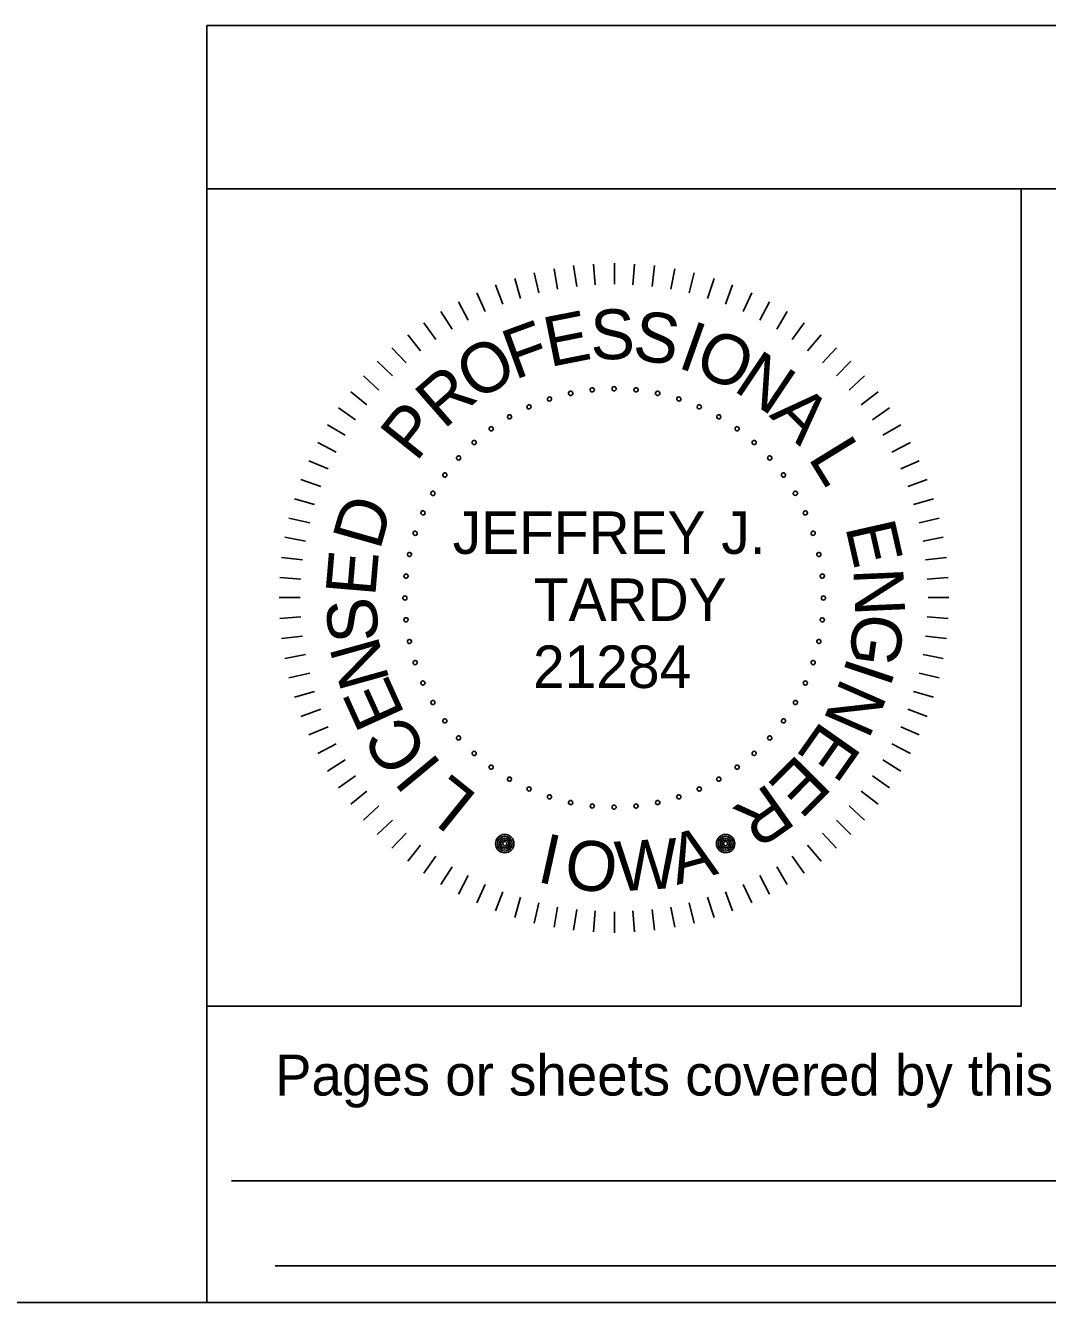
# Model space of a CAD drawing. Extents: x -2096698 to 6160, y -2144490 to 6200.
# Drawn here: x 5321.7 to 5625.4, y 4209 to 4588.6 of the extents above; entities that cross this region are included whole.
import ezdxf

# ---------------------------------------------------------------- set-up
doc = ezdxf.new("R2010")
doc.units = 0
doc.layers.add('Level 15', color=7, linetype='Continuous')
doc.layers.add('Level 2', color=7, linetype='Continuous')

msp = doc.modelspace()

# ---------------------------------------------------------------- linework, layer by layer
at = {"layer": 'Level 15'}
msp.add_line((3074.9, 4208.97), (6131.53, 4208.97), dxfattribs=at)
at = {"layer": 'Level 2'}
for p, q in [((5375.6, 4540.02), (6131.53, 4540.02)), ((5617.5, 4297.05), (5617.5, 4540.02)), ((5496.67, 4511.73), (5496.67, 4517.93)), ((5496.67, 4511.73), (5496.67, 4517.93)), ((5474.21, 4509.11), (5472.79, 4515.07)), ((5474.21, 4509.11), (5472.79, 4515.07)), ((5479.71, 4510.28), (5478.75, 4516.26)), ((5479.71, 4510.28), (5478.75, 4516.26)), ((5485.46, 4511.01), (5484.48, 4517.23)), ((5485.46, 4511.01), (5484.48, 4517.23)), ((5490.94, 4511.5), (5490.47, 4517.69)), ((5490.94, 4511.5), (5490.47, 4517.69)), ((5502.17, 4511.5), (5502.66, 4517.69)), ((5502.17, 4511.5), (5502.66, 4517.69)), ((5507.92, 4511.01), (5508.62, 4517.23)), ((5507.92, 4511.01), (5508.62, 4517.23)), ((5513.4, 4510.28), (5514.6, 4516.26)), ((5513.4, 4510.28), (5514.6, 4516.26)), ((5518.89, 4509.11), (5520.33, 4515.07)), ((5518.89, 4509.11), (5520.33, 4515.07)), ((5463.47, 4505.74), (5461.31, 4511.5)), ((5463.47, 4505.74), (5461.31, 4511.5)), ((5468.72, 4507.43), (5467.04, 4513.4)), ((5468.72, 4507.43), (5467.04, 4513.4)), ((5524.38, 4507.43), (5526.29, 4513.4)), ((5524.38, 4507.43), (5526.29, 4513.4)), ((5529.67, 4505.74), (5531.8, 4511.5)), ((5529.67, 4505.74), (5531.8, 4511.5)), ((5453.2, 4500.98), (5450.33, 4506.48)), ((5453.2, 4500.98), (5450.33, 4506.48)), ((5458.22, 4503.6), (5455.83, 4509.11)), ((5458.22, 4503.6), (5455.83, 4509.11)), ((5534.92, 4503.6), (5537.54, 4509.11)), ((5534.92, 4503.6), (5537.54, 4509.11)), ((5539.93, 4500.98), (5542.8, 4506.48)), ((5539.93, 4500.98), (5542.8, 4506.48)), ((5448.42, 4498.34), (5445.06, 4503.6)), ((5448.42, 4498.34), (5445.06, 4503.6)), ((5544.95, 4498.34), (5548.05, 4503.6)), ((5544.95, 4498.34), (5548.05, 4503.6)), ((5443.63, 4495.23), (5440.07, 4500.25)), ((5443.63, 4495.23), (5440.07, 4500.25)), ((5549.48, 4495.23), (5553.07, 4500.25)), ((5549.48, 4495.23), (5553.07, 4500.25)), ((5439.08, 4491.9), (5435.28, 4496.68)), ((5439.08, 4491.9), (5435.28, 4496.68)), ((5554.01, 4491.9), (5558.08, 4496.68)), ((5554.01, 4491.9), (5558.08, 4496.68)), ((5434.78, 4488.3), (5430.5, 4492.84)), ((5434.78, 4488.3), (5430.5, 4492.84)), ((5558.55, 4488.3), (5562.62, 4492.84)), ((5558.55, 4488.3), (5562.62, 4492.84)), ((5430.73, 4484.49), (5426.19, 4488.79)), ((5430.73, 4484.49), (5426.19, 4488.79)), ((5562.62, 4484.49), (5566.92, 4488.79)), ((5562.62, 4484.49), (5566.92, 4488.79)), ((5426.66, 4480.18), (5422.14, 4484.49)), ((5426.66, 4480.18), (5422.14, 4484.49)), ((5566.44, 4480.18), (5570.98, 4484.49)), ((5566.44, 4480.18), (5570.98, 4484.49)), ((5423.09, 4475.88), (5418.32, 4479.72)), ((5423.09, 4475.88), (5418.32, 4479.72)), ((5570.03, 4475.88), (5575.06, 4479.72)), ((5570.03, 4475.88), (5575.06, 4479.72)), ((5419.75, 4471.35), (5414.71, 4474.93)), ((5419.75, 4471.35), (5414.71, 4474.93)), ((5573.37, 4471.35), (5578.38, 4474.93)), ((5573.37, 4471.35), (5578.38, 4474.93)), ((5416.63, 4466.82), (5411.38, 4469.92)), ((5416.63, 4466.82), (5411.38, 4469.92)), ((5576.47, 4466.82), (5581.74, 4469.92)), ((5576.47, 4466.82), (5581.74, 4469.92)), ((5414, 4461.8), (5408.52, 4464.67)), ((5414, 4461.8), (5408.52, 4464.67)), ((5579.11, 4461.8), (5584.62, 4464.67)), ((5579.11, 4461.8), (5584.62, 4464.67)), ((5411.61, 4456.78), (5405.89, 4459.17)), ((5411.61, 4456.78), (5405.89, 4459.17)), ((5581.74, 4456.78), (5587.24, 4459.17)), ((5581.74, 4456.78), (5587.24, 4459.17)), ((5409.46, 4451.53), (5403.5, 4453.67)), ((5409.46, 4451.53), (5403.5, 4453.67)), ((5583.88, 4451.53), (5589.63, 4453.67)), ((5583.88, 4451.53), (5589.63, 4453.67)), ((5407.56, 4446.24), (5401.58, 4447.93)), ((5407.56, 4446.24), (5401.58, 4447.93)), ((5585.56, 4446.24), (5591.54, 4447.93)), ((5585.56, 4446.24), (5591.54, 4447.93)), ((5406.13, 4440.76), (5399.91, 4442.2)), ((5406.13, 4440.76), (5399.91, 4442.2)), ((5587.24, 4440.76), (5593.2, 4442.2)), ((5587.24, 4440.76), (5593.2, 4442.2)), ((5404.91, 4435.27), (5398.72, 4436.46)), ((5404.91, 4435.27), (5398.72, 4436.46)), ((5588.42, 4435.27), (5594.4, 4436.46)), ((5588.42, 4435.27), (5594.4, 4436.46)), ((5403.97, 4429.78), (5397.76, 4430.48)), ((5403.97, 4429.78), (5397.76, 4430.48)), ((5589.15, 4429.78), (5595.36, 4430.48)), ((5589.15, 4429.78), (5595.36, 4430.48)), ((5403.5, 4424.04), (5397.27, 4424.52)), ((5403.5, 4424.04), (5397.27, 4424.52)), ((5589.63, 4424.04), (5595.83, 4424.52)), ((5589.63, 4424.04), (5595.83, 4424.52)), ((5403.26, 4418.54), (5397.04, 4418.54)), ((5403.26, 4418.54), (5397.04, 4418.54)), ((5589.87, 4418.54), (5596.06, 4418.54)), ((5589.87, 4418.54), (5596.06, 4418.54)), ((5403.5, 4412.81), (5397.27, 4412.33)), ((5403.5, 4412.81), (5397.27, 4412.33)), ((5589.63, 4412.81), (5595.83, 4412.33)), ((5589.63, 4412.81), (5595.83, 4412.33)), ((5403.97, 4407.08), (5397.76, 4406.34)), ((5403.97, 4407.08), (5397.76, 4406.34)), ((5589.15, 4407.08), (5595.36, 4406.34)), ((5589.15, 4407.08), (5595.36, 4406.34)), ((5404.91, 4401.58), (5398.72, 4400.38)), ((5404.91, 4401.58), (5398.72, 4400.38)), ((5588.42, 4401.58), (5594.4, 4400.38)), ((5588.42, 4401.58), (5594.4, 4400.38)), ((5406.13, 4396.08), (5399.91, 4394.66)), ((5406.13, 4396.08), (5399.91, 4394.66)), ((5587.24, 4396.08), (5593.2, 4394.66)), ((5587.24, 4396.08), (5593.2, 4394.66)), ((5407.56, 4390.58), (5401.58, 4388.9)), ((5407.56, 4390.58), (5401.58, 4388.9)), ((5585.56, 4390.58), (5591.54, 4388.9)), ((5585.56, 4390.58), (5591.54, 4388.9)), ((5409.46, 4385.33), (5403.5, 4383.18)), ((5409.46, 4385.33), (5403.5, 4383.18)), ((5583.88, 4385.33), (5589.63, 4383.18)), ((5583.88, 4385.33), (5589.63, 4383.18)), ((5411.61, 4380.08), (5405.89, 4377.69)), ((5411.61, 4380.08), (5405.89, 4377.69)), ((5581.74, 4380.08), (5587.24, 4377.69)), ((5581.74, 4380.08), (5587.24, 4377.69)), ((5414, 4375.07), (5408.52, 4372.2)), ((5414, 4375.07), (5408.52, 4372.2)), ((5579.11, 4375.07), (5584.62, 4372.2)), ((5579.11, 4375.07), (5584.62, 4372.2)), ((5416.63, 4370.28), (5411.38, 4366.93)), ((5416.63, 4370.28), (5411.38, 4366.93)), ((5576.47, 4370.28), (5581.74, 4366.93)), ((5576.47, 4370.28), (5581.74, 4366.93)), ((5419.75, 4365.5), (5414.71, 4361.93)), ((5419.75, 4365.5), (5414.71, 4361.93)), ((5573.37, 4365.5), (5578.38, 4361.93)), ((5573.37, 4365.5), (5578.38, 4361.93)), ((5423.09, 4360.95), (5418.32, 4357.15)), ((5423.09, 4360.95), (5418.32, 4357.15)), ((5570.03, 4360.95), (5575.06, 4357.15)), ((5570.03, 4360.95), (5575.06, 4357.15)), ((5426.66, 4356.64), (5422.14, 4352.37)), ((5426.66, 4356.64), (5422.14, 4352.37)), ((5566.44, 4356.64), (5570.98, 4352.37)), ((5566.44, 4356.64), (5570.98, 4352.37)), ((5430.73, 4352.37), (5426.19, 4348.06)), ((5430.73, 4352.37), (5426.19, 4348.06)), ((5562.62, 4352.37), (5566.92, 4348.06)), ((5562.62, 4352.37), (5566.92, 4348.06)), ((5434.78, 4348.53), (5430.5, 4344)), ((5434.78, 4348.53), (5430.5, 4344)), ((5558.55, 4348.53), (5562.62, 4344)), ((5558.55, 4348.53), (5562.62, 4344)), ((5439.08, 4344.96), (5435.28, 4340.18)), ((5439.08, 4344.96), (5435.28, 4340.18)), ((5554.01, 4344.96), (5558.08, 4340.18)), ((5554.01, 4344.96), (5558.08, 4340.18)), ((5443.63, 4341.61), (5440.07, 4336.58)), ((5443.63, 4341.61), (5440.07, 4336.58)), ((5549.48, 4341.61), (5553.07, 4336.58)), ((5549.48, 4341.61), (5553.07, 4336.58)), ((5448.42, 4338.49), (5445.06, 4333.24)), ((5448.42, 4338.49), (5445.06, 4333.24)), ((5453.2, 4335.87), (5450.33, 4330.38)), ((5453.2, 4335.87), (5450.33, 4330.38)), ((5539.93, 4335.87), (5542.8, 4330.38)), ((5539.93, 4335.87), (5542.8, 4330.38)), ((5544.95, 4338.49), (5548.05, 4333.24)), ((5544.95, 4338.49), (5548.05, 4333.24)), ((5458.22, 4333.24), (5455.83, 4327.76)), ((5458.22, 4333.24), (5455.83, 4327.76)), ((5534.92, 4333.24), (5537.54, 4327.76)), ((5534.92, 4333.24), (5537.54, 4327.76)), ((5463.47, 4331.08), (5461.31, 4325.37)), ((5463.47, 4331.08), (5461.31, 4325.37)), ((5468.72, 4329.42), (5467.04, 4323.44)), ((5468.72, 4329.42), (5467.04, 4323.44)), ((5524.38, 4329.42), (5526.29, 4323.44)), ((5524.38, 4329.42), (5526.29, 4323.44)), ((5529.67, 4331.08), (5531.8, 4325.37)), ((5529.67, 4331.08), (5531.8, 4325.37)), ((5474.21, 4327.76), (5472.79, 4321.78)), ((5474.21, 4327.76), (5472.79, 4321.78)), ((5479.71, 4326.54), (5478.75, 4320.58)), ((5479.71, 4326.54), (5478.75, 4320.58)), ((5485.46, 4325.83), (5484.48, 4319.62)), ((5485.46, 4325.83), (5484.48, 4319.62)), ((5490.94, 4325.37), (5490.47, 4319.14)), ((5490.94, 4325.37), (5490.47, 4319.14)), ((5496.67, 4325.12), (5496.67, 4318.9)), ((5496.67, 4325.12), (5496.67, 4318.9)), ((5502.17, 4325.37), (5502.66, 4319.14)), ((5502.17, 4325.37), (5502.66, 4319.14)), ((5507.92, 4325.83), (5508.62, 4319.62)), ((5507.92, 4325.83), (5508.62, 4319.62)), ((5513.4, 4326.54), (5514.6, 4320.58)), ((5513.4, 4326.54), (5514.6, 4320.58)), ((5518.89, 4327.76), (5520.33, 4321.78)), ((5518.89, 4327.76), (5520.33, 4321.78)), ((5375.6, 4297.05), (5617.5, 4297.05)), ((5382.93, 4245.18), (6123.89, 4245.18)), ((5395.82, 4219.87), (6111.37, 4219.87))]:
    msp.add_line(p, q, dxfattribs=at)
msp.add_lwpolyline([(5375.6, 4588.62), (6131.53, 4588.62), (6131.53, 4208.97), (5375.6, 4208.97)], close=True, dxfattribs=at)
for centre, radius in [((5464.09, 4345.38), 2.73), ((5464.09, 4345.38), 2.73), ((5464.09, 4345.38), 2.19), ((5464.09, 4345.38), 2.19), ((5464.09, 4345.38), 1.64), ((5464.09, 4345.38), 1.64), ((5529.72, 4345.38), 2.73), ((5529.72, 4345.38), 2.73), ((5529.72, 4345.38), 2.19), ((5529.72, 4345.38), 2.19), ((5529.72, 4345.38), 1.64), ((5529.72, 4345.38), 1.64), ((5464.09, 4345.38), 1.17), ((5464.09, 4345.38), 1.17), ((5529.72, 4345.38), 1.17), ((5529.72, 4345.38), 1.17)]:
    msp.add_circle(centre, radius, dxfattribs=at)
for centre, start, end in [((5483.66, 4479.27), 12, 192), ((5483.66, 4479.27), 12, 192), ((5490.09, 4480.29), 6, 186), ((5490.09, 4480.29), 6, 186), ((5490.09, 4480.29), 186, 6), ((5490.09, 4480.29), 186, 6), ((5496.59, 4480.63), 0, 180), ((5496.59, 4480.63), 0, 180), ((5496.59, 4480.63), 180, 0), ((5496.59, 4480.63), 180, 0), ((5503.1, 4480.29), 174, 354), ((5503.1, 4480.29), 174, 354), ((5503.1, 4480.29), 354, 174), ((5503.1, 4480.29), 354, 174), ((5509.53, 4479.27), 348, 168), ((5509.53, 4479.27), 348, 168), ((5477.37, 4477.58), 18, 198), ((5477.37, 4477.58), 18, 198), ((5477.37, 4477.58), 198, 18), ((5477.37, 4477.58), 198, 18), ((5483.66, 4479.27), 192, 12), ((5483.66, 4479.27), 192, 12), ((5509.53, 4479.27), 168, 348), ((5509.53, 4479.27), 168, 348), ((5515.81, 4477.58), 162, 342), ((5515.81, 4477.58), 162, 342), ((5515.81, 4477.58), 342, 162), ((5515.81, 4477.58), 342, 162), ((5465.5, 4472.3), 30, 210), ((5465.5, 4472.3), 30, 210), ((5465.5, 4472.3), 210, 30), ((5465.5, 4472.3), 210, 30), ((5471.3, 4475.25), 24, 204), ((5471.3, 4475.25), 24, 204), ((5471.3, 4475.25), 204, 24), ((5471.3, 4475.25), 204, 24), ((5521.89, 4475.25), 156, 336), ((5521.89, 4475.25), 156, 336), ((5521.89, 4475.25), 336, 156), ((5521.89, 4475.25), 336, 156), ((5527.69, 4472.3), 150, 330), ((5527.69, 4472.3), 150, 330), ((5527.69, 4472.3), 330, 150), ((5527.69, 4472.3), 330, 150), ((5460.04, 4468.75), 36, 216), ((5460.04, 4468.75), 36, 216), ((5460.04, 4468.75), 216, 36), ((5460.04, 4468.75), 216, 36), ((5533.15, 4468.75), 144, 324), ((5533.15, 4468.75), 144, 324), ((5533.15, 4468.75), 324, 144), ((5533.15, 4468.75), 324, 144), ((5454.98, 4464.65), 42, 222), ((5454.98, 4464.65), 42, 222), ((5454.98, 4464.65), 222, 42), ((5454.98, 4464.65), 222, 42), ((5538.21, 4464.65), 138, 318), ((5538.21, 4464.65), 138, 318), ((5538.21, 4464.65), 318, 138), ((5538.21, 4464.65), 318, 138), ((5450.37, 4460.05), 48, 228), ((5450.37, 4460.05), 48, 228), ((5450.37, 4460.05), 228, 48), ((5450.37, 4460.05), 228, 48), ((5542.82, 4460.05), 132, 312), ((5542.82, 4460.05), 132, 312), ((5542.82, 4460.05), 312, 132), ((5542.82, 4460.05), 312, 132), ((5446.28, 4454.99), 54, 234), ((5446.28, 4454.99), 54, 234), ((5446.28, 4454.99), 234, 54), ((5446.28, 4454.99), 234, 54), ((5546.91, 4454.99), 126, 306), ((5546.91, 4454.99), 126, 306), ((5546.91, 4454.99), 306, 126), ((5546.91, 4454.99), 306, 126), ((5442.73, 4449.53), 60, 240), ((5442.73, 4449.53), 60, 240), ((5442.73, 4449.53), 240, 60), ((5442.73, 4449.53), 240, 60), ((5550.46, 4449.53), 120, 300), ((5550.46, 4449.53), 120, 300), ((5550.46, 4449.53), 300, 120), ((5550.46, 4449.53), 300, 120), ((5439.77, 4443.73), 66, 246), ((5439.77, 4443.73), 66, 246), ((5439.77, 4443.73), 246, 66), ((5439.77, 4443.73), 246, 66), ((5553.41, 4443.73), 114, 294), ((5553.41, 4443.73), 114, 294), ((5553.41, 4443.73), 294, 114), ((5553.41, 4443.73), 294, 114), ((5437.44, 4437.65), 72, 252), ((5437.44, 4437.65), 72, 252), ((5437.44, 4437.65), 252, 72), ((5437.44, 4437.65), 252, 72), ((5555.75, 4437.65), 108, 288), ((5555.75, 4437.65), 108, 288), ((5555.75, 4437.65), 288, 108), ((5555.75, 4437.65), 288, 108), ((5435.76, 4431.36), 78, 258), ((5435.76, 4431.36), 78, 258), ((5435.76, 4431.36), 258, 78), ((5435.76, 4431.36), 258, 78), ((5557.43, 4431.36), 102, 282), ((5557.43, 4431.36), 102, 282), ((5557.43, 4431.36), 282, 102), ((5557.43, 4431.36), 282, 102), ((5434.74, 4424.93), 84, 264), ((5434.74, 4424.93), 84, 264), ((5434.74, 4424.93), 264, 84), ((5434.74, 4424.93), 264, 84), ((5558.45, 4424.93), 96, 276), ((5558.45, 4424.93), 96, 276), ((5558.45, 4424.93), 276, 96), ((5558.45, 4424.93), 276, 96), ((5434.4, 4418.43), 90, 270), ((5434.4, 4418.43), 90, 270), ((5434.4, 4418.43), 270, 90), ((5434.4, 4418.43), 270, 90), ((5558.79, 4418.43), 90, 270), ((5558.79, 4418.43), 90, 270), ((5558.79, 4418.43), 270, 90), ((5558.79, 4418.43), 270, 90), ((5434.74, 4411.93), 96, 276), ((5434.74, 4411.93), 96, 276), ((5434.74, 4411.93), 276, 96), ((5434.74, 4411.93), 276, 96), ((5558.45, 4411.93), 84, 264), ((5558.45, 4411.93), 84, 264), ((5558.45, 4411.93), 264, 84), ((5558.45, 4411.93), 264, 84), ((5435.76, 4405.5), 102, 282), ((5435.76, 4405.5), 102, 282), ((5435.76, 4405.5), 282, 102), ((5435.76, 4405.5), 282, 102), ((5557.43, 4405.5), 78, 258), ((5557.43, 4405.5), 78, 258), ((5557.43, 4405.5), 258, 78), ((5557.43, 4405.5), 258, 78), ((5437.44, 4399.21), 108, 288), ((5437.44, 4399.21), 108, 288), ((5437.44, 4399.21), 288, 108), ((5437.44, 4399.21), 288, 108), ((5555.75, 4399.21), 72, 252), ((5555.75, 4399.21), 72, 252), ((5555.75, 4399.21), 252, 72), ((5555.75, 4399.21), 252, 72), ((5439.77, 4393.13), 114, 294), ((5439.77, 4393.13), 114, 294), ((5439.77, 4393.13), 294, 114), ((5439.77, 4393.13), 294, 114), ((5553.41, 4393.13), 66, 246), ((5553.41, 4393.13), 66, 246), ((5553.41, 4393.13), 246, 66), ((5553.41, 4393.13), 246, 66), ((5442.73, 4387.33), 120, 300), ((5442.73, 4387.33), 120, 300), ((5442.73, 4387.33), 300, 120), ((5442.73, 4387.33), 300, 120), ((5550.46, 4387.33), 60, 240), ((5550.46, 4387.33), 60, 240), ((5550.46, 4387.33), 240, 60), ((5550.46, 4387.33), 240, 60), ((5446.28, 4381.87), 126, 306), ((5446.28, 4381.87), 126, 306), ((5446.28, 4381.87), 306, 126), ((5446.28, 4381.87), 306, 126), ((5546.91, 4381.87), 54, 234), ((5546.91, 4381.87), 54, 234), ((5546.91, 4381.87), 234, 54), ((5546.91, 4381.87), 234, 54), ((5450.37, 4376.81), 312, 132), ((5450.37, 4376.81), 312, 132), ((5542.82, 4376.81), 48, 228), ((5542.82, 4376.81), 48, 228), ((5450.37, 4376.81), 132, 312), ((5450.37, 4376.81), 132, 312), ((5542.82, 4376.81), 228, 48), ((5542.82, 4376.81), 228, 48), ((5454.98, 4372.21), 138, 318), ((5454.98, 4372.21), 138, 318), ((5454.98, 4372.21), 318, 138), ((5454.98, 4372.21), 318, 138), ((5538.21, 4372.21), 42, 222), ((5538.21, 4372.21), 42, 222), ((5538.21, 4372.21), 222, 42), ((5538.21, 4372.21), 222, 42), ((5460.04, 4368.11), 144, 324), ((5460.04, 4368.11), 144, 324), ((5460.04, 4368.11), 324, 144), ((5460.04, 4368.11), 324, 144), ((5533.15, 4368.11), 36, 216), ((5533.15, 4368.11), 36, 216), ((5533.15, 4368.11), 216, 36), ((5533.15, 4368.11), 216, 36), ((5465.5, 4364.57), 150, 330), ((5465.5, 4364.57), 150, 330), ((5465.5, 4364.57), 330, 150), ((5465.5, 4364.57), 330, 150), ((5471.3, 4361.61), 336, 156), ((5471.3, 4361.61), 336, 156), ((5521.89, 4361.61), 24, 204), ((5521.89, 4361.61), 24, 204), ((5527.69, 4364.57), 30, 210), ((5527.69, 4364.57), 30, 210), ((5527.69, 4364.57), 210, 30), ((5527.69, 4364.57), 210, 30), ((5471.3, 4361.61), 156, 336), ((5471.3, 4361.61), 156, 336), ((5477.37, 4359.28), 162, 342), ((5477.37, 4359.28), 162, 342), ((5477.37, 4359.28), 342, 162), ((5477.37, 4359.28), 342, 162), ((5515.81, 4359.28), 18, 198), ((5515.81, 4359.28), 18, 198), ((5515.81, 4359.28), 198, 18), ((5515.81, 4359.28), 198, 18), ((5521.89, 4361.61), 204, 24), ((5521.89, 4361.61), 204, 24), ((5483.66, 4357.59), 168, 348), ((5483.66, 4357.59), 168, 348), ((5483.66, 4357.59), 348, 168), ((5483.66, 4357.59), 348, 168), ((5490.09, 4356.57), 354, 174), ((5490.09, 4356.57), 354, 174), ((5490.09, 4356.57), 174, 354), ((5490.09, 4356.57), 174, 354), ((5496.59, 4356.23), 0, 180), ((5496.59, 4356.23), 0, 180), ((5496.59, 4356.23), 180, 0), ((5496.59, 4356.23), 180, 0), ((5503.1, 4356.57), 6, 186), ((5503.1, 4356.57), 6, 186), ((5503.1, 4356.57), 186, 6), ((5503.1, 4356.57), 186, 6), ((5509.53, 4357.59), 12, 192), ((5509.53, 4357.59), 12, 192), ((5509.53, 4357.59), 192, 12), ((5509.53, 4357.59), 192, 12), ((5464.1, 4345.38), 162, 342), ((5464.1, 4345.38), 162, 342), ((5464.1, 4345.38), 342, 162), ((5464.1, 4345.38), 342, 162), ((5529.71, 4345.38), 18, 198), ((5529.71, 4345.38), 18, 198), ((5529.71, 4345.38), 198, 18), ((5529.71, 4345.38), 198, 18)]:
    msp.add_arc(centre, 0.622, start, end, dxfattribs=at)

# ---------------------------------------------------------------- texts
for s, height, rotation, p in [('E', 14.81, 11.2738, (5477.42, 4487.04)), ('E', 14.81, 11.2738, (5477.42, 4487.04)), ('S', 14.82, 1.2097, (5489.66, 4489.28)), ('S', 14.82, 1.2097, (5489.66, 4489.28)), ('S', 14.82, 351.581, (5501.7, 4489.46)), ('S', 14.82, 351.581, (5501.7, 4489.46)), ('F', 14.82, 20.1324, (5467.03, 4483.21)), ('F', 14.82, 20.1324, (5467.03, 4483.21)), ('I', 14.82, 340.4982, (5515.03, 4487.06)), ('I', 14.82, 340.4982, (5515.03, 4487.06)), ('O', 14.82, 336.5548, (5519.71, 4485.64)), ('O', 14.82, 336.5548, (5519.71, 4485.64)), ('O', 14.82, 30.8566, (5455.5, 4476.69)), ('O', 14.82, 30.8566, (5455.5, 4476.69)), ('N', 14.82, 326.1481, (5531.65, 4480.3)), ('N', 14.82, 326.1481, (5531.65, 4480.3)), ('R', 14.82, 41.1423, (5445.97, 4468.31)), ('R', 14.82, 41.1423, (5445.97, 4468.31)), ('A', 14.82, 315.3556, (5542.45, 4472.57)), ('A', 14.82, 315.3556, (5542.45, 4472.57)), ('P', 14.82, 51.428, (5437.73, 4458.61)), ('P', 14.82, 51.428, (5437.73, 4458.61)), ('L', 14.82, 301.5966, (5554.01, 4460.12)), ('L', 14.82, 301.5966, (5554.01, 4460.12)), ('D', 14.82, 74.1417, (5426.95, 4432.32)), ('D', 14.82, 74.1417, (5426.95, 4432.32)), ('JEFFREY J.', 12.639, 0, (5448.62, 4431.52)), ('E', 14.82, 282.8045, (5565.23, 4439.58)), ('E', 14.82, 282.8045, (5565.23, 4439.58)), ('E', 14.82, 85.1868, (5425.58, 4418.65)), ('E', 14.82, 85.1868, (5425.58, 4418.65)), ('TARDY', 12.639, 0, (5472.74, 4411.59)), ('N', 14.82, 272.5188, (5567.66, 4427.1)), ('N', 14.82, 272.5188, (5567.66, 4427.1)), ('S', 14.82, 95.4878, (5426.81, 4405.93)), ('S', 14.82, 95.4878, (5426.81, 4405.93)), ('G', 14.82, 262.2331, (5568.26, 4414.43)), ('G', 14.82, 262.2331, (5568.26, 4414.43)), ('N', 14.82, 105.5518, (5429.96, 4393.9)), ('N', 14.82, 105.5518, (5429.96, 4393.9)), ('21284', 12.639, 0, (5472.49, 4391.66)), ('I', 14.82, 251.5089, (5566.16, 4401.37)), ('I', 14.82, 251.5089, (5566.16, 4401.37)), ('E', 14.82, 114.4105, (5434.54, 4383.81)), ('E', 14.82, 114.4105, (5434.54, 4383.81)), ('N', 14.82, 246.3457, (5564.32, 4395.14)), ('N', 14.82, 246.3457, (5564.32, 4395.14)), ('C', 14.82, 125.1347, (5441.89, 4372.8)), ('C', 14.82, 125.1347, (5441.89, 4372.8)), ('E', 14.82, 234.9185, (5558.31, 4382.35)), ('E', 14.82, 234.9185, (5558.31, 4382.35)), ('I', 14.82, 129.6827, (5445.74, 4368.8)), ('I', 14.82, 129.6827, (5445.74, 4368.8)), ('E', 14.82, 225.1168, (5551.26, 4372.41)), ('E', 14.82, 225.1168, (5551.26, 4372.41)), ('L', 14.82, 141.1019, (5456.4, 4359.49)), ('L', 14.82, 141.1019, (5456.4, 4359.49)), ('R', 14.82, 215.3403, (5542.54, 4363.66)), ('R', 14.82, 215.3403, (5542.54, 4363.66)), ('I', 14.81, 347.5793, (5473.26, 4334.13)), ('I', 14.81, 347.5793, (5473.26, 4334.13)), ('W', 14.82, 3.4332, (5497.25, 4331.15)), ('W', 14.82, 3.4332, (5497.25, 4331.15)), ('A', 14.82, 15.2001, (5515.18, 4333.04)), ('A', 14.82, 15.2001, (5515.18, 4333.04)), ('O', 14.82, 352.9458, (5481.31, 4332.34)), ('O', 14.82, 352.9458, (5481.31, 4332.34)), ('Pages or sheets covered by this seal:', 12.1488, 0, (5395.82, 4270.49))]:
    msp.add_text(s, height=height, rotation=rotation, dxfattribs=at).set_placement(p)

doc.saveas('drawing.dxf')
